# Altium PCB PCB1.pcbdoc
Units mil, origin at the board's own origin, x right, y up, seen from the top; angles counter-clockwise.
Board outline 1838 x 1812 mil, 2 copper layers (Top Layer, Bottom Layer); 12 components, 20 nets, 53 pads, 79 vias.
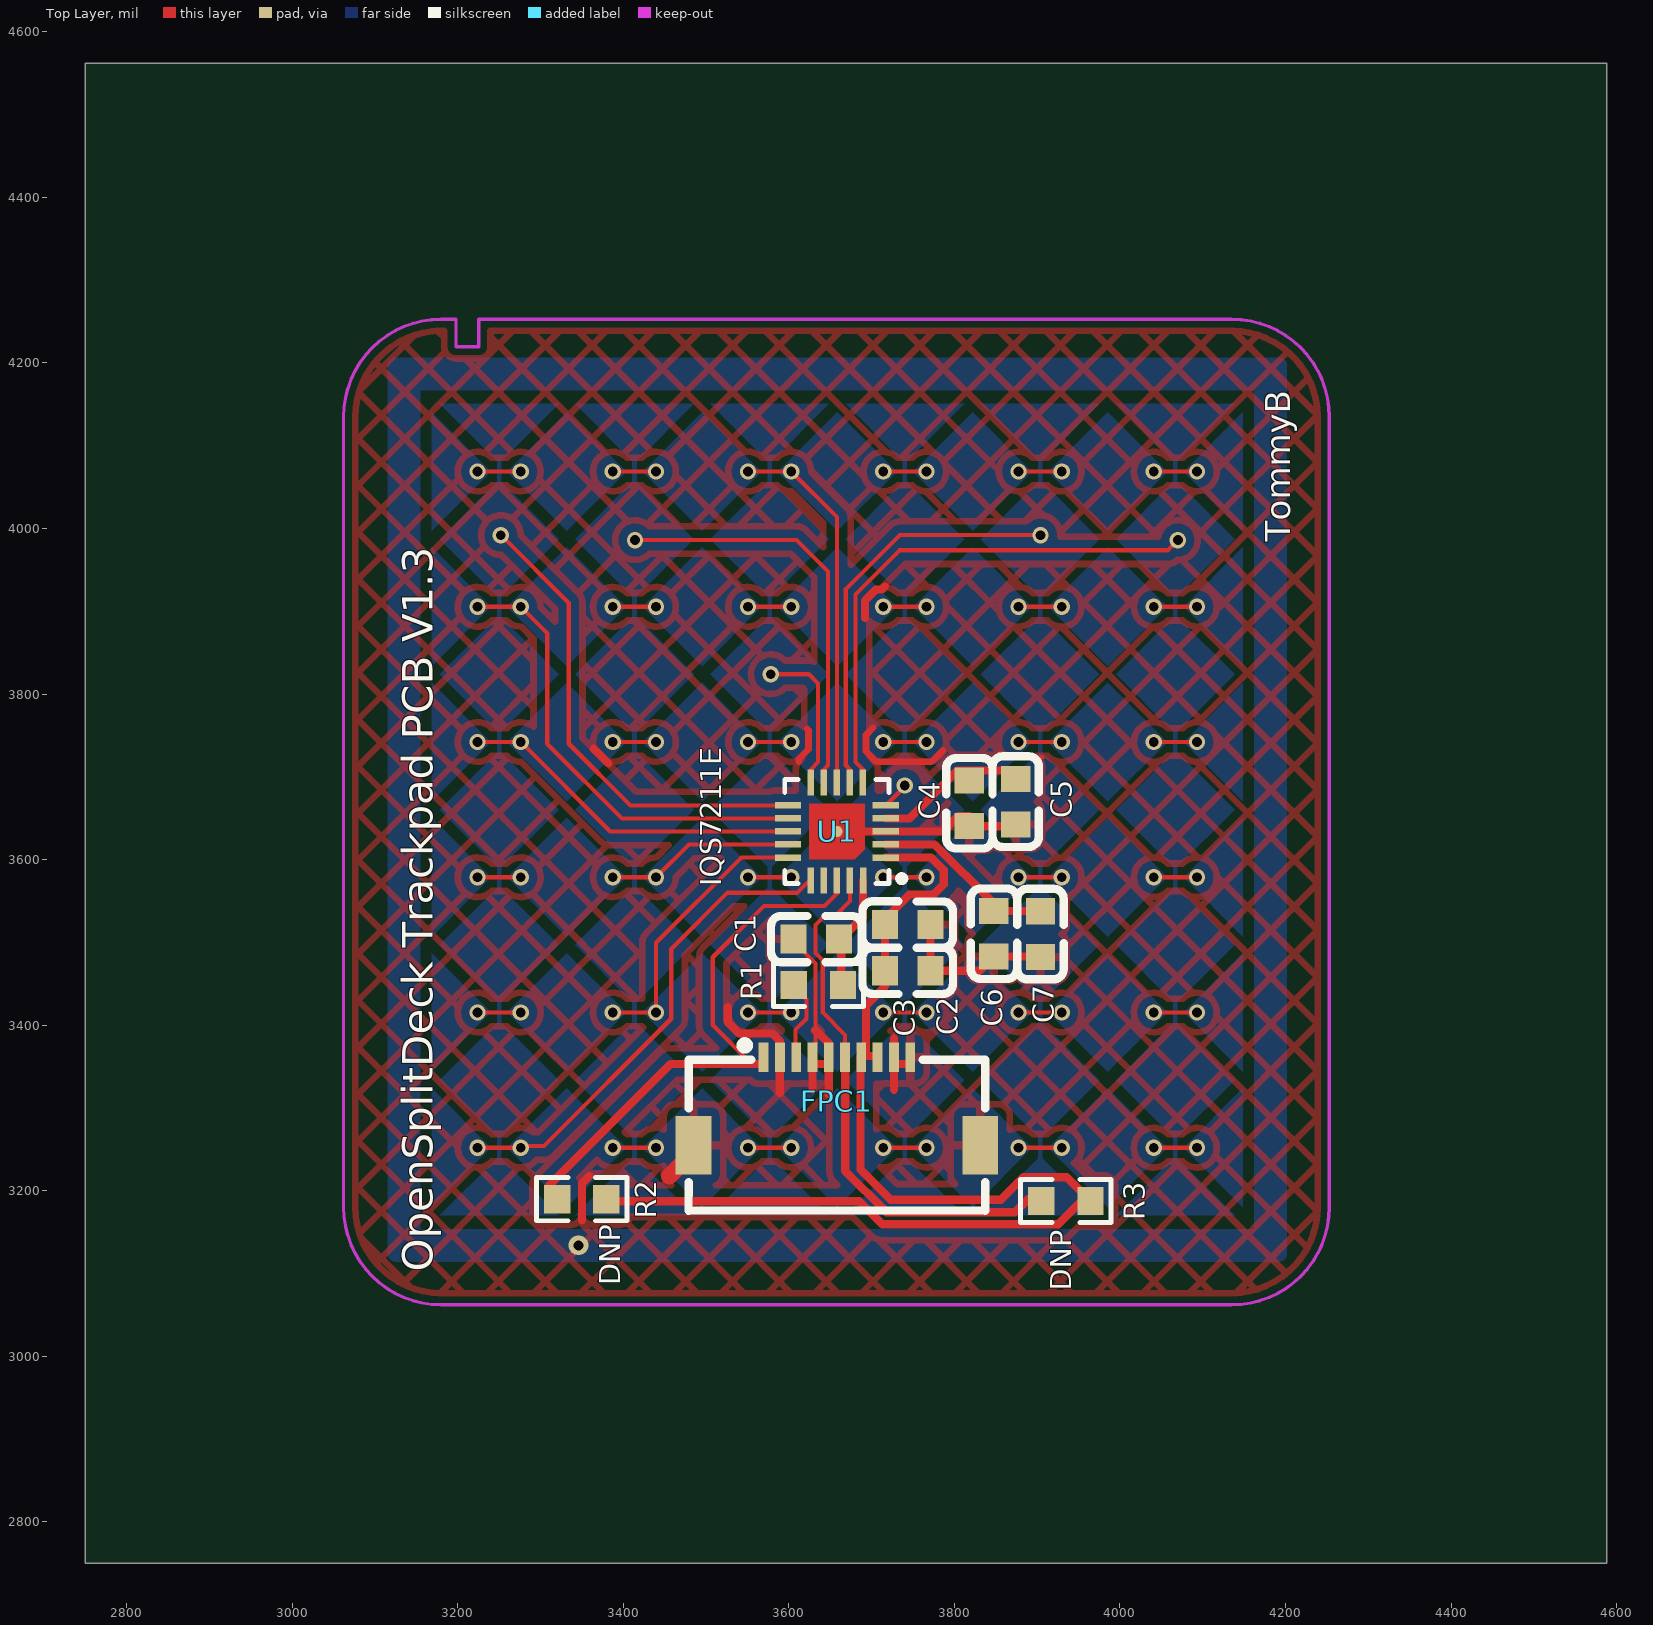
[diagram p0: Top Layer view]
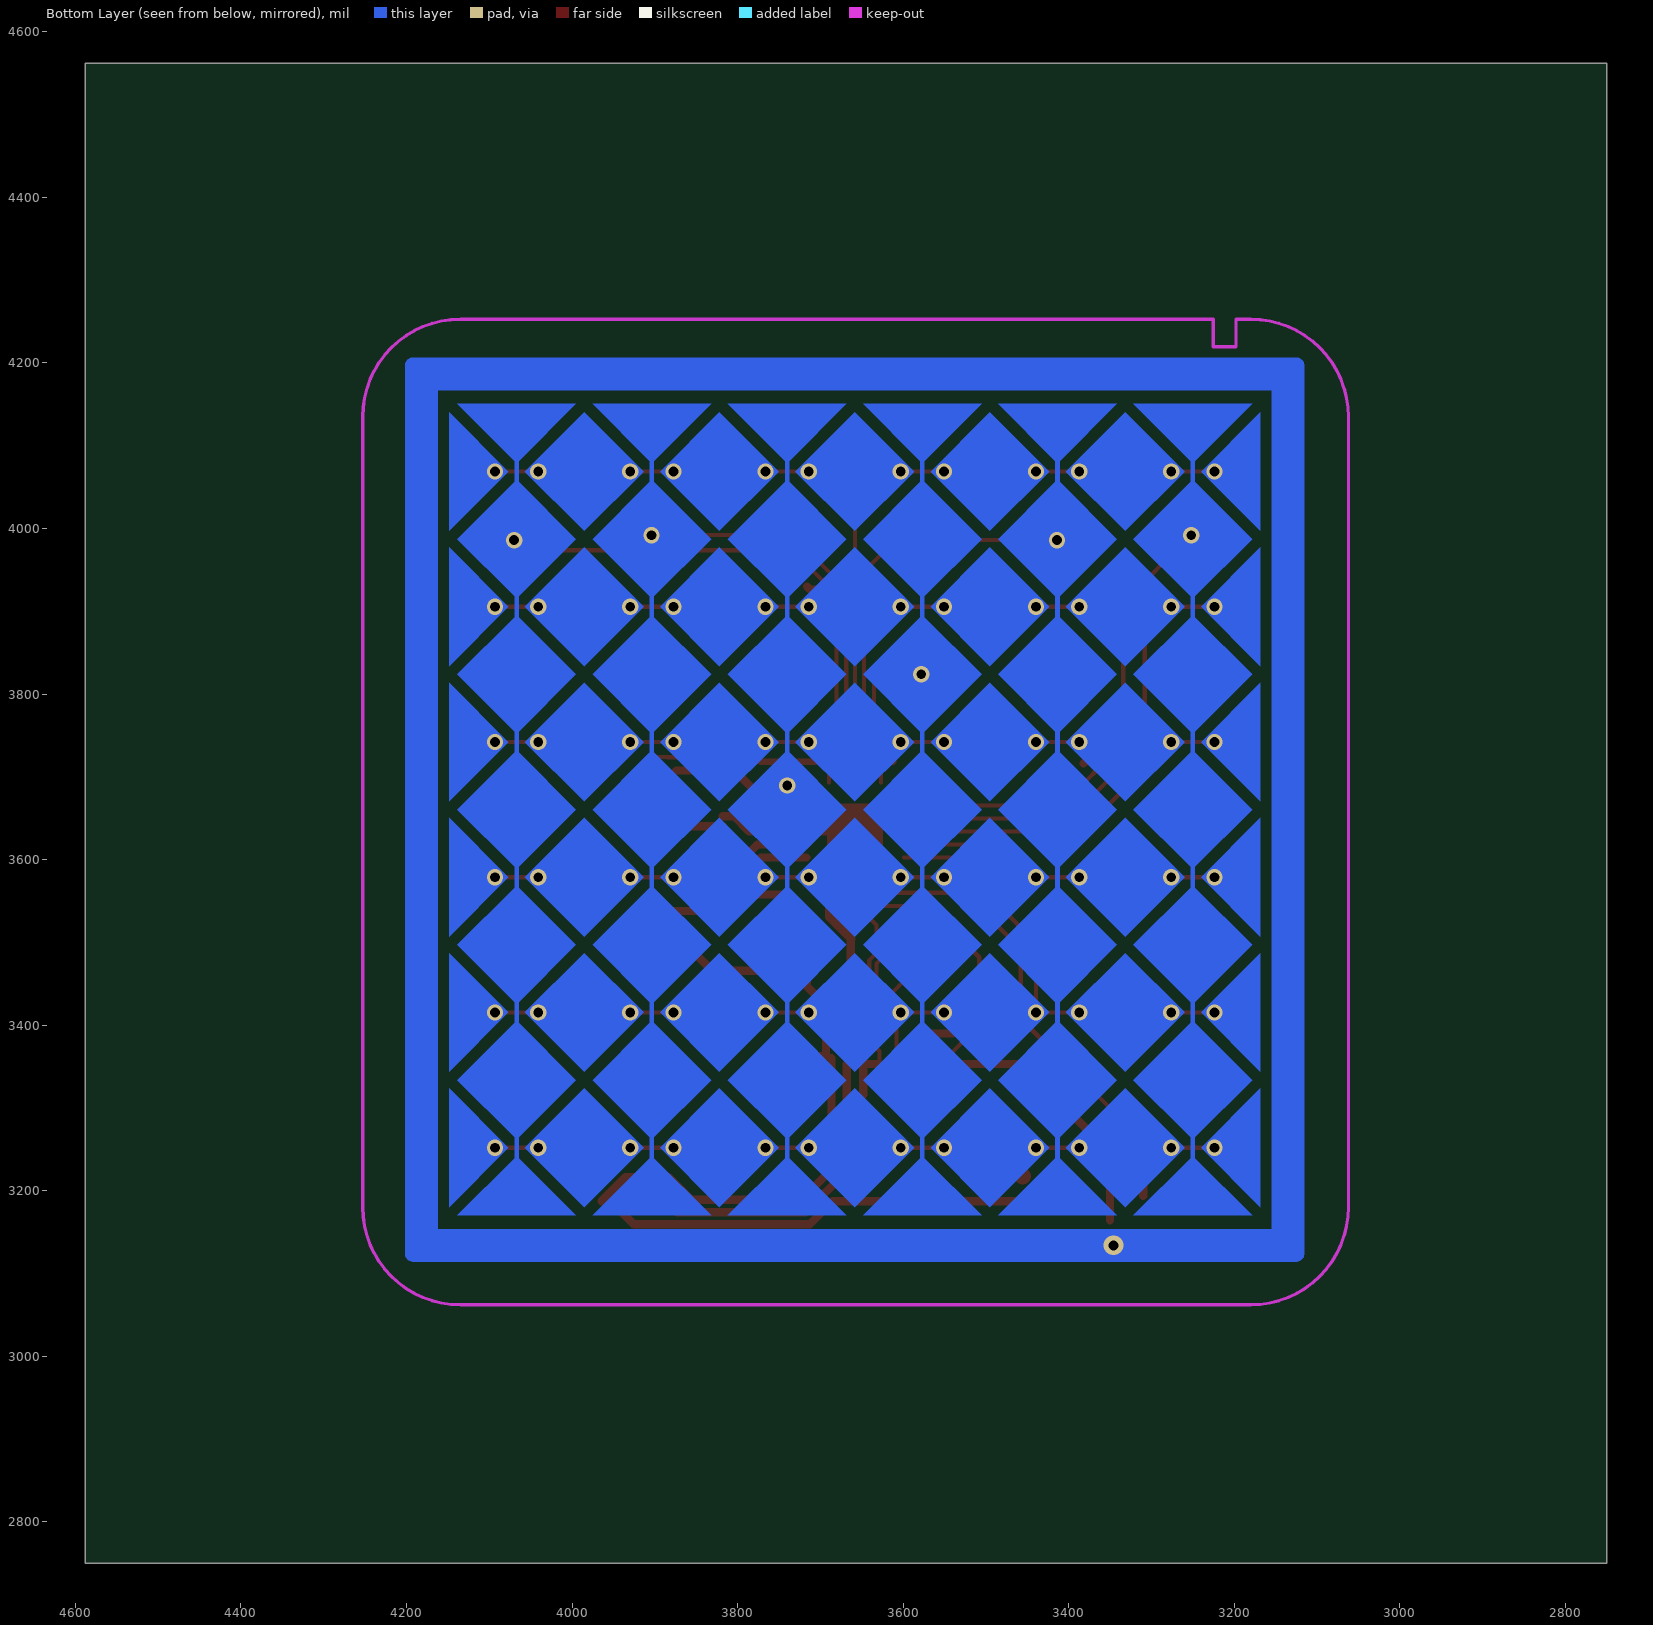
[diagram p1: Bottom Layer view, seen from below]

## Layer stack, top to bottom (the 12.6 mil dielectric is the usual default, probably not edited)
Top Layer: signal copper (thickness not stored)
Dielectric: dielectric 12.6, FR-4, Dk 4.8
Bottom Layer: signal copper (thickness not stored)

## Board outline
4588,2750 2750,2750 2750,4562 4588,4562

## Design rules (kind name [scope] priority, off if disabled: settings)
BoardOutlineClearance copperThickness1oz [All] p0: genericclearance=10 ignorepadtopadclearanceinfootprint=FALSE except(0: Arc-SplitContinuation Track-SplitContinuation SMDPad-SplitContinuation THPad-SplitContinuation Via-SplitContinuation Fill-SplitContinuation Poly-SplitContinuation Region-SplitContinuation Text-SplitContinuation; 6: Track-CutoutEdge SMDPad-CutoutEdge THPad-CutoutEdge Via-CutoutEdge Region-CutoutEdge; 11.8: Track-OutlineEdge SMDPad-OutlineEdge THPad-OutlineEdge Via-OutlineEdge Fill-OutlineEdge Region-OutlineEdge Poly-OutlineEdge Text-OutlineEdge Fill-CutoutEdge)
BoardOutlineClearance copperThickness2oz [All] p0: genericclearance=10 ignorepadtopadclearanceinfootprint=FALSE except(0: Arc-SplitContinuation Track-SplitContinuation SMDPad-SplitContinuation THPad-SplitContinuation Via-SplitContinuation Fill-SplitContinuation Poly-SplitContinuation Region-SplitContinuation Text-SplitContinuation; 6: Track-CutoutEdge SMDPad-CutoutEdge THPad-CutoutEdge Via-CutoutEdge Region-CutoutEdge; 11.8: Track-OutlineEdge SMDPad-OutlineEdge THPad-OutlineEdge Via-OutlineEdge Fill-OutlineEdge Region-OutlineEdge Poly-OutlineEdge Text-OutlineEdge Fill-CutoutEdge)
Clearance copperThickness1oz [(InNet('GND') OR InNet('VCC') OR InNet('RX0') OR InNet('RX1') OR InNet('RX2') OR InNet('RX3') OR InNet('RX4') OR InNet('$1N1973') OR InNet('$1N1718') OR InNet('$1N1697') OR InNet('RX5') OR InNet('TX6') OR InNet('TX8') OR InNet('TX9') OR InNet('TX10') OR InNet('TX11') OR InNet('TX7') OR InNet('SCL') OR InNet('SDA') OR InNet('RDY'))] p1: gap=7 ignorepadtopadclearanceinfootprint=FALSE except(4: Track-Track; 6: Track-SMDPad SMDPad-SMDPad Track-THPad SMDPad-THPad THPad-THPad Track-Via SMDPad-Via THPad-Via Via-Via SMDPad-Fill THPad-Fill Via-Fill Fill-Fill Track-Region SMDPad-Region THPad-Region Via-Region Region-Region Track-Poly SMDPad-Poly THPad-Poly Via-Poly Fill-Poly Region-Poly Poly-Poly Track-Text SMDPad-Text THPad-Text Via-Text Fill-Text Region-Text Poly-Text Text-Text; 6.9: Track-Hole SMDPad-Hole THPad-Hole Via-Hole Fill-Hole Region-Hole Poly-Hole Text-Hole Sheet-Hole; 11.8: Track-Fill Fill-Region Track-Sheet SMDPad-Sheet THPad-Sheet Via-Sheet Fill-Sheet Region-Sheet Poly-Sheet Text-Sheet)
Clearance copperThickness2oz [All] p1: gap=7 ignorepadtopadclearanceinfootprint=FALSE except(6: Track-SMDPad SMDPad-SMDPad Track-THPad SMDPad-THPad THPad-THPad Track-Via SMDPad-Via THPad-Via Via-Via SMDPad-Fill THPad-Fill Via-Fill Fill-Fill Track-Region SMDPad-Region THPad-Region Via-Region Region-Region Track-Poly SMDPad-Poly THPad-Poly Via-Poly Fill-Poly Region-Poly Poly-Poly Track-Text SMDPad-Text THPad-Text Via-Text Fill-Text Region-Text Poly-Text Text-Text; 6.9: Track-Hole SMDPad-Hole THPad-Hole Via-Hole Fill-Hole Region-Hole Poly-Hole Text-Hole Sheet-Hole; 8: Track-Track; 11.8: Track-Fill Fill-Region Track-Sheet SMDPad-Sheet THPad-Sheet Via-Sheet Fill-Sheet Region-Sheet Poly-Sheet Text-Sheet)
DiffPairsRouting differentialPair [All] p1: maxuncoupledlength=10 minlimit=6 maxlimit=6 mostfreqgap=6 toplayer_minwidth=5 toplayer_prefwidth=10 toplayer_maxwidth=100 bottomlayer_minwidth=5 bottomlayer_prefwidth=10 bottomlayer_maxwidth=100
PasteMaskExpansion pasteMaskExpansion [All] p1: expansion=0
PlaneConnect innerPlane [All] p1: planeconnectstyle=Relief reliefexpansion=20 reliefentries=4 reliefconductorwidth=10 reliefairgap=10
PolygonConnect copperRegion [All] p1: connectstyle=Relief reliefentries=4 reliefconductorwidth=10 polygonreliefangle="90 Angle" airgapwidth=10
RoutingVias viaSize [All] p1: viastyle="Through Hole" holewidth=12.0078 minholewidth=11.811 maxholewidth=248.0314 width=24.0158 minwidth=19.685 maxwidth=393.7008
SolderMaskExpansion solderMaskExpansion [All] p1: useseparateexpansions=TRUE expansion=2 expansionbottom=2
Width copperThickness1oz [All] p1: maxlimit=100 minlimit=5 preferedwidth=10
Width copperThickness2oz [All] p1: maxlimit=100 minlimit=8 preferedwidth=10

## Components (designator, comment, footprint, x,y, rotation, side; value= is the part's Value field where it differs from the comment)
C1 "CL10B104KA8NNNC" C0603 3633.12,3504 r0 top
C2 "CL10A475KP8NNNC" C0603 3743.56,3521.56 r180 top
C3 "CC0603JRNPO9BN101" C0603 3743.56,3465.56 r180 top
C4 "CC0603JRNPO9BN101" C0603 3818,3668 r90 top
C5 "CL10A225KP8NNNC" C0603 3874,3670 r90 top
C6 "CC0603JRNPO9BN101" C0603 3847.56,3510.44 r90 top
C7 "CL10A225KP8NNNC" C0603 3904,3510 r90 top
FPC1 "FPC-05F-10PH15" FPC-SMD_10P-P0.50_XUNPU_FPC-05F-10PH15 3658,3308 r0 top
R1 "0603WAF4701T5E" R0603 3635.66,3448.34 r180 top
R2 "0603WAF4701T5E" R0603 3349.66,3189.66 r0 top
R3 "0603WAF4701T5E" R0603 3934.64,3187.32 r0 top
U1 "IQS7211E" UQFN-20_L3.0-W3.0-P0.40-BL-EP1.7 3658,3634 r90 top

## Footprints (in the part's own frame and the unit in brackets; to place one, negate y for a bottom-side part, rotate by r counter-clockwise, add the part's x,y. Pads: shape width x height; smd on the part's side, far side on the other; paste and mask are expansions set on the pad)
C0603 [mm]
  rect 0.8x0.9 smd: 1(-0.7,0) 2(0.7,0)
  silkscreen extent -1.39,-0.71 1.39,0.71
FPC-SMD_10P-P0.50_XUNPU_FPC-05F-10PH15 [mm]
  rect 0.3x0.9 smd: 1(-2.25,1.35) 2(-1.75,1.35) 3(-1.25,1.35) 4(-0.75,1.35) 5(-0.25,1.35) 6(0.25,1.35) 7(0.75,1.35) 8(1.25,1.35) 9(1.75,1.35) 10(2.25,1.35)
  rect 1.1x1.8 smd: 11(4.4,-1.35) 12(-4.4,-1.35)
  silkscreen extent -4.56,-3.36 4.55,1.84
R0603 [mil]
  rect 31.75x34.02 smd: 1(-29.66,0) 2(29.66,0)
  silkscreen extent -55,-26 55,26
UQFN-20_L3.0-W3.0-P0.40-BL-EP1.7 [mm]
  rect 0.2x0.8 smd: 1(-0.8,-1.5) 2(-0.4,-1.5) 3(0,-1.5) 4(0.4,-1.5) 5(0.8,-1.5) 11(0.8,1.5) 12(0.4,1.5) 13(0,1.5) 14(-0.4,1.5) 15(-0.8,1.5)
  rect 0.8x0.2 smd: 6(1.5,-0.8) 7(1.5,-0.4) 8(1.5,0) 9(1.5,0.4) 10(1.5,0.8) 16(-1.5,0.8) 17(-1.5,0.4) 18(-1.5,0) 19(-1.5,-0.4) 20(-1.5,-0.802)
  round 0.34 smd: 21(0,0)
  Top Layer region: 0.85,0.85 0.85,-0.85 -0.55,-0.85 -0.85,-0.55 -0.85,0.85
  silkscreen extent -1.6,-2.09 1.6,1.6

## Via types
v1: diameter 19.7, hole 11.8, Top Layer to Bottom Layer, 78 vias
v2: diameter 24.02, hole 12.01, Top Layer to Bottom Layer, 1 vias

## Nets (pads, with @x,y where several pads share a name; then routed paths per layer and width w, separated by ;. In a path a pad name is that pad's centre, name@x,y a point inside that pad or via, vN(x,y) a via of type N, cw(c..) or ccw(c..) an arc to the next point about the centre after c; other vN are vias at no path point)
$1N1697: C6.2 C7.2 U1.2 | length 225.4
  Top Layer w10: U1.2 3775.96,3618.26 3847.56,3546.65 C6.2 3903.56,3538 C7.2
$1N1718: C4.2 C5.2 U1.4 | length 180.9
  Top Layer w10: U1.4 3745.74,3649.74 3803.56,3707.56 3818,3707.56 C5.2@3874,3707.56
$1N1973: C1.2 R1.1 U1.20 | length 138
  Top Layer w10: R1.1@3663.32,3448.34 3663.32,3503.36 3662.68,3504 3689.27,3530.59 3689.27,3543.83 3689.57,3544.12 U1.20
GND: C1.1 C2.1 C3.1 C4.1 C5.1 C6.1 C7.1 FPC1.2 FPC1.4 FPC1.5 FPC1.9 FPC1.10 FPC1.11 FPC1.12 U1.3 U1.21 | length 1367.1
  Top Layer w5: C1.1 3605.56,3500.91 3632,3474.47 3632,3394 3632,3372 3628.47,3368.47 FPC1.4@3628.47,3353.15 ; 3854,3728 3862,3728 3866,3724 3869.54,3724 3869.82,3723.71 3885.01,3723.71 3885.3,3724 3906,3724
  Top Layer w8: 3612,3718 3612,3721.7 3623.71,3733.42 3623.71,3756.29 3622,3758 ; 3702,3759.48 3693.2,3750.68 3693.2,3730.8 3706,3718 3772,3718 3786,3732
  Top Layer w10: 3350,3164 3350,3208.76 3358.89,3217.65 ; 3364,3734 3382,3716 ; 3526,3422 3526,3404 3540,3390 3580,3390 3589.1,3380.9 3589.1,3353.15 3589.1,3318 ; 3628.47,3322 3628.47,3353.15 FPC1.5@3648.16,3353.15 ; 3632,3394 3648.16,3377.84 FPC1.5@3648.16,3353.15 ; 3648.16,3316 FPC1.5@3648.16,3353.15 ; U1.21 U1.3 3785.99,3633.99 3804.44,3652.44 C4.1@3818,3652.44 ; 3692,3892 3692,3912.86 3705.4,3926.27 3712.27,3926.27 3716,3930 ; 3726.9,3322 FPC1.9@3726.9,3353.15 ; 3726.9,3384 FPC1.9@3726.9,3353.15 ; FPC1.10@3746.58,3353.15 FPC1.9@3726.9,3353.15 ; C2.1 C3.1 3830.24,3465.56 C6.1 3903.56,3482.88 C7.1 C7.1@3904.49,3482.93 ; C4.1 3872,3640.44 C5.1
  Top Layer w20: 3455.57,3217.65 FPC1.12@3484.77,3246.85
  other v2: 3346,3134
RDY: FPC1.3 R1.2 | length 108.1
  Top Layer w5: R1.2@3604,3448.34 3621.21,3431.13 3621.21,3407.68 3608,3394.47 3608,3353.94 FPC1.3@3608.79,3353.15
RX0: U1.5 | length 33.5
  Top Layer w5: U1.5 3740,3688.45 v1(3740,3689.51)
RX1: U1.6 | length 647.8
  Top Layer w5: U1.6 3689.49,3708.99 3680.48,3718 3680.48,3920.48 3733.67,3973.67 4057.67,3973.67 v1(4070,3986)
RX2: U1.7 | length 498
  Top Layer w5: U1.7 3673.74,3709 3668.74,3714 3668.74,3926.74 3734,3992 v1(3904,3992)
RX3: U1.11 | length 581.8
  Top Layer w5: v1(3252,3992) 3334,3910 3334,3740 3408.51,3665.49 U1.11
RX4: U1.9 | length 506
  Top Layer w5: v1(3414,3986) 3609.25,3986 3647.26,3948 3647.26,3713.99 3642.26,3708.99 U1.9
RX5: U1.10 | length 185.2
  Top Layer w5: v1(3578,3824) 3624.01,3824 3635.23,3812.77 3635.23,3717.71 3626.51,3708.99 U1.10
SCL: FPC1.1 R2.1 U1.18 | length 678.8
  Top Layer w5: 3554.85,3353.15 3508,3400 3508,3482 3570,3544 3643,3544 3658.01,3559 U1.18
  Top Layer w10: R2.1@3310,3193.66 3310,3206 3457.15,3353.15 3554.85,3353.15 FPC1.1@3569.42,3353.15
SDA: FPC1.6 R3.1 U1.19 | length 655.8
  Top Layer w5: FPC1.6@3667.84,3353.15 3667.84,3388.16 3640.96,3415.04 3640.96,3478.26 3632,3487.22 3632,3520.78 3641.42,3530.2 3654.2,3530.2 3673.76,3549.76 U1.19
  Top Layer w10: FPC1.6@3667.84,3353.15 3668,3353.15 3668,3224 3718,3174 3873.07,3174 3888.61,3189.54 3902.76,3189.54 R3.1
TX6: U1.8 | length 712
  Top Layer w5: v1(3223.88,4068.82) v1(3276.11,4068.82) ; v1(3387.26,4068.82) v1(3439.49,4068.82) ; v1(3550.65,4068.82) v1(3602.88,4068.82) 3658.01,4013.69 U1.8 ; v1(3714.03,4068.82) v1(3766.27,4068.82) ; v1(3877.42,4068.82) v1(3929.65,4068.82) ; v1(4040.8,4068.82) v1(4093.04,4068.82)
TX7: U1.12 | length 820.4
  Top Layer w5: v1(3223.88,3905.43) v1(3276.11,3905.43) 3308,3873.54 3308,3740 3398.26,3649.74 U1.12 ; v1(3387.26,3905.43) v1(3439.49,3905.43) ; v1(3550.65,3905.43) v1(3602.88,3905.43) ; v1(3714.03,3905.43) v1(3766.27,3905.43) ; v1(3877.42,3905.43) v1(3929.65,3905.43) ; v1(4040.8,3905.43) v1(4093.04,3905.43)
TX8: U1.13 | length 681
  Top Layer w5: v1(3223.88,3742.05) v1(3276.11,3742.05) 3384.16,3633.99 U1.13 ; v1(3387.26,3742.05) v1(3439.49,3742.05) ; v1(3550.65,3742.05) v1(3602.88,3742.05) ; v1(3714.03,3742.05) v1(3766.27,3742.05) ; v1(3877.42,3742.05) v1(3929.65,3742.05) ; v1(4040.8,3742.05) v1(4093.04,3742.05)
TX9: U1.14 | length 489.3
  Top Layer w5: v1(3223.88,3578.66) v1(3276.11,3578.66) ; v1(3387.26,3578.66) v1(3439.49,3578.66) 3479.09,3618.26 U1.14 ; v1(3550.65,3578.66) v1(3602.88,3578.66) ; v1(3714.03,3578.66) v1(3766.27,3578.66) ; v1(3877.42,3578.66) v1(3929.65,3578.66) ; v1(4040.8,3578.66) v1(4093.04,3578.66)
TX10: U1.15 | length 599.7
  Top Layer w5: v1(3223.88,3415.27) v1(3276.11,3415.27) ; v1(3387.26,3415.27) v1(3439.49,3415.27) 3439.49,3499.49 3542.51,3602.51 U1.15 ; v1(3550.65,3415.27) v1(3602.88,3415.27) ; v1(3714.03,3415.27) v1(3766.27,3415.27) ; v1(3877.42,3415.27) v1(3929.65,3415.27) ; v1(4040.8,3415.27) v1(4093.04,3415.27)
TX11: U1.16 | length 846.9
  Top Layer w5: v1(3223.88,3251.89) v1(3276.11,3251.89) 3278.11,3253.89 3304.04,3253.89 3457.83,3407.68 3457.83,3491.83 3526,3560 3610.15,3560 3625.09,3574.95 U1.16 ; v1(3387.26,3251.89) v1(3439.49,3251.89) ; v1(3550.65,3251.89) v1(3602.88,3251.89) ; v1(3714.03,3251.89) v1(3766.27,3251.89) ; v1(3877.42,3251.89) v1(3929.65,3251.89) ; v1(4040.8,3251.89) v1(4093.04,3251.89)
VCC: C2.2 C3.2 FPC1.7 FPC1.8 R2.2 R3.2 U1.1 | length 1428.9
  Top Layer w10: R2.2 3381.66,3187.32 3684.86,3187.32 3712.85,3159.33 3925.41,3159.33 3953.4,3187.32 R3.2 3935.31,3216.31 3883.55,3216.31 3856.26,3189.02 3722.81,3189.02 3686.53,3225.29 FPC1.7@3686.53,3359.82 ; FPC1.8@3705.56,3362.8 3693.2,3362.8 3693.2,3423.9 3716,3446.71 C3.2 3716,3528 3745.83,3557.83 3774.9,3557.83 3787.1,3570.03 3787.1,3587.29 3771.89,3602.51 U1.1
pads on no net: U1.17

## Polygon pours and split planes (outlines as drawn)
GND on Top Layer (hatched 45Degree grid 40 track 8, remove dead copper, pour order 0): 3000,4312 4338,4312 4338,3000 3000,3000

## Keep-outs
Board Outline Layer:
  lines w3.94: 3062,3180.11 3062,4134.83 cw(c3180.11,4134.83) 3180.11,4252.94 3197.83,4252.94 3197.83,4219.57 3225.39,4219.57 3225.39,4252.94 4134.83,4252.94 cw(c4134.83,4134.83) 4252.94,4134.83 4252.94,3180.11 cw(c4134.83,3180.11) 4134.83,3062 3180.11,3062 cw(c3180.11,3180.11) 3062,3180.11

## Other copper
Bottom Layer:
  region net GND: 3125.15,4206.54 4191.76,4206.54 cw(c4191.76,4196.54) 4201.76,4196.54 4201.76,4177.17 cw(c4191.76,4177.17) 4191.76,4167.17 3125.15,4167.17 cw(c3125.15,4177.17) 3115.15,4177.17 3115.15,4196.54 cw(c3125.15,4196.54)
  region net GND: 4172.39,4206.54 4191.76,4206.54 cw(c4191.76,4196.54) 4201.76,4196.54 4201.76,3124.17 cw(c4191.76,3124.17) 4191.76,3114.17 4172.39,3114.17 cw(c4172.39,3124.17) 4162.39,3124.17 4162.39,4196.54 cw(c4172.39,4196.54)
  region net GND: 3125.15,3153.54 4191.76,3153.54 cw(c4191.76,3143.54) 4201.76,3143.54 4201.76,3124.17 cw(c4191.76,3124.17) 4191.76,3114.17 3125.15,3114.17 cw(c3125.15,3124.17) 3115.15,3124.17 3115.15,3143.54 cw(c3125.15,3143.54)
  region net GND: 3125.15,4206.54 3144.52,4206.54 cw(c3144.52,4196.54) 3154.52,4196.54 3154.52,3124.17 cw(c3144.52,3124.17) 3144.52,3114.17 3125.15,3114.17 cw(c3125.15,3124.17) 3115.15,3124.17 3115.15,4196.54 cw(c3125.15,4196.54)
  region net RX3: 3178.31,3170.2 3321.68,3170.2 3252.51,3239.36 3252.51,3264.42 3321.68,3333.58 3252.51,3402.75 3252.51,3427.8 3321.68,3496.97 3252.51,3566.13 3252.51,3591.19 3321.68,3660.35 3252.51,3729.52 3252.51,3754.57 3321.68,3823.74 3252.51,3892.9 3252.51,3917.96 3321.68,3987.12 3252.51,4056.29 3252.51,4081.34 3321.68,4150.51 3178.31,4150.51 3247.47,4081.34 3247.47,4056.29 3178.31,3987.12 3247.47,3917.96 3247.47,3892.9 3178.31,3823.74 3247.47,3754.57 3247.47,3729.52 3178.31,3660.35 3247.47,3591.19 3247.47,3566.13 3178.31,3496.97 3247.47,3427.8 3247.47,3402.75 3178.31,3333.58 3247.47,3264.42 3247.47,3239.36
  region net TX11: 3331.68,3180.2 3260,3251.89 3331.68,3323.57 3403.37,3251.89
  region net TX11: 3168.3,3180.2 3239.98,3251.89 3168.3,3323.57
  region net RX4: 3341.69,3170.2 3485.06,3170.2 3415.9,3239.36 3415.9,3264.42 3485.06,3333.58 3415.9,3402.75 3415.9,3427.8 3485.06,3496.97 3415.9,3566.13 3415.9,3591.19 3485.06,3660.35 3415.9,3729.52 3415.9,3754.57 3485.06,3823.74 3415.9,3892.9 3415.9,3917.96 3485.06,3987.12 3415.9,4056.29 3415.9,4081.34 3485.06,4150.51 3341.69,4150.51 3410.86,4081.34 3410.86,4056.29 3341.69,3987.12 3410.86,3917.96 3410.86,3892.9 3341.69,3823.74 3410.86,3754.57 3410.86,3729.52 3341.69,3660.35 3410.86,3591.19 3410.86,3566.13 3341.69,3496.97 3410.86,3427.8 3410.86,3402.75 3341.69,3333.58 3410.86,3264.42 3410.86,3239.36
  region net TX11: 3495.07,3180.2 3423.39,3251.89 3495.07,3323.57 3566.76,3251.89
  region net RX5: 3505.08,3170.2 3648.45,3170.2 3579.28,3239.36 3579.28,3264.42 3648.45,3333.58 3579.28,3402.75 3579.28,3427.8 3648.45,3496.97 3579.28,3566.13 3579.28,3591.19 3648.45,3660.35 3579.28,3729.52 3579.28,3754.57 3648.45,3823.74 3579.28,3892.9 3579.28,3917.96 3648.45,3987.12 3579.28,4056.29 3579.28,4081.34 3648.45,4150.51 3505.08,4150.51 3574.24,4081.34 3574.24,4056.29 3505.08,3987.12 3574.24,3917.96 3574.24,3892.9 3505.08,3823.74 3574.24,3754.57 3574.24,3729.52 3505.08,3660.35 3574.24,3591.19 3574.24,3566.13 3505.08,3496.97 3574.24,3427.8 3574.24,3402.75 3505.08,3333.58 3574.24,3264.42 3574.24,3239.36
  region net TX11: 3658.46,3180.2 3586.77,3251.89 3658.46,3323.57 3730.14,3251.89
  region net RX0: 3668.46,3170.2 3811.83,3170.2 3742.67,3239.36 3742.67,3264.42 3811.83,3333.58 3742.67,3402.75 3742.67,3427.8 3811.83,3496.97 3742.67,3566.13 3742.67,3591.19 3811.83,3660.35 3742.67,3729.52 3742.67,3754.57 3811.83,3823.74 3742.67,3892.9 3742.67,3917.96 3811.83,3987.12 3742.67,4056.29 3742.67,4081.34 3811.83,4150.51 3668.46,4150.51 3737.63,4081.34 3737.63,4056.29 3668.46,3987.12 3737.63,3917.96 3737.63,3892.9 3668.46,3823.74 3737.63,3754.57 3737.63,3729.52 3668.46,3660.35 3737.63,3591.19 3737.63,3566.13 3668.46,3496.97 3737.63,3427.8 3737.63,3402.75 3668.46,3333.58 3737.63,3264.42 3737.63,3239.36
  region net TX11: 3821.84,3180.2 3750.16,3251.89 3821.84,3323.57 3893.53,3251.89
  region net RX2: 3831.85,3170.2 3975.22,3170.2 3906.06,3239.36 3906.06,3264.42 3975.22,3333.58 3906.06,3402.75 3906.06,3427.8 3975.22,3496.97 3906.06,3566.13 3906.06,3591.19 3975.22,3660.35 3906.06,3729.52 3906.06,3754.57 3975.22,3823.74 3906.06,3892.9 3906.06,3917.96 3975.22,3987.12 3906.06,4056.29 3906.06,4081.34 3975.22,4150.51 3831.85,4150.51 3901.02,4081.34 3901.02,4056.29 3831.85,3987.12 3901.02,3917.96 3901.02,3892.9 3831.85,3823.74 3901.02,3754.57 3901.02,3729.52 3831.85,3660.35 3901.02,3591.19 3901.02,3566.13 3831.85,3496.97 3901.02,3427.8 3901.02,3402.75 3831.85,3333.58 3901.02,3264.42 3901.02,3239.36
  region net TX11: 3985.23,3180.2 3913.54,3251.89 3985.23,3323.57 4056.91,3251.89
  region net RX1: 3995.24,3170.2 4138.61,3170.2 4069.44,3239.36 4069.44,3264.42 4138.61,3333.58 4069.44,3402.75 4069.44,3427.8 4138.61,3496.97 4069.44,3566.13 4069.44,3591.19 4138.61,3660.35 4069.44,3729.52 4069.44,3754.57 4138.61,3823.74 4069.44,3892.9 4069.44,3917.96 4138.61,3987.12 4069.44,4056.29 4069.44,4081.34 4138.61,4150.51 3995.24,4150.51 4064.4,4081.34 4064.4,4056.29 3995.24,3987.12 4064.4,3917.96 4064.4,3892.9 3995.24,3823.74 4064.4,3754.57 4064.4,3729.52 3995.24,3660.35 4064.4,3591.19 4064.4,3566.13 3995.24,3496.97 4064.4,3427.8 4064.4,3402.75 3995.24,3333.58 4064.4,3264.42 4064.4,3239.36
  region net TX11: 4148.61,3323.57 4076.93,3251.89 4148.61,3180.2
  region net TX10: 3168.3,3343.59 3239.98,3415.27 3168.3,3486.96
  region net TX10: 3331.68,3343.59 3260,3415.27 3331.68,3486.96 3403.37,3415.27
  region net TX10: 3495.07,3343.59 3423.39,3415.27 3495.07,3486.96 3566.76,3415.27
  region net TX10: 3658.46,3343.59 3586.77,3415.27 3658.46,3486.96 3730.14,3415.27
  region net TX10: 3821.84,3343.59 3750.16,3415.27 3821.84,3486.96 3893.53,3415.27
  region net TX10: 3985.23,3343.59 3913.54,3415.27 3985.23,3486.96 4056.91,3415.27
  region net TX10: 4148.61,3486.96 4076.93,3415.27 4148.61,3343.59
  region net TX9: 3168.3,3506.97 3239.98,3578.66 3168.3,3650.34
  region net TX9: 3331.68,3506.97 3260,3578.66 3331.68,3650.34 3403.37,3578.66
  region net TX9: 3495.07,3506.97 3423.39,3578.66 3495.07,3650.34 3566.76,3578.66
  region net TX9: 3658.46,3506.97 3586.77,3578.66 3658.46,3650.34 3730.14,3578.66
  region net TX9: 3821.84,3506.97 3750.16,3578.66 3821.84,3650.34 3893.53,3578.66
  region net TX9: 3985.23,3506.97 3913.54,3578.66 3985.23,3650.34 4056.91,3578.66
  region net TX9: 4148.61,3650.34 4076.93,3578.66 4148.61,3506.97
  region net TX8: 3168.3,3670.36 3239.98,3742.05 3168.3,3813.73
  region net TX8: 3331.68,3670.36 3260,3742.05 3331.68,3813.73 3403.37,3742.05
  region net TX8: 3495.07,3670.36 3423.39,3742.05 3495.07,3813.73 3566.76,3742.05
  region net TX8: 3658.46,3670.36 3586.77,3742.05 3658.46,3813.73 3730.14,3742.05
  region net TX8: 3821.84,3670.36 3750.16,3742.05 3821.84,3813.73 3893.53,3742.05
  region net TX8: 3985.23,3670.36 3913.54,3742.05 3985.23,3813.73 4056.91,3742.05
  region net TX8: 4148.61,3813.73 4076.93,3742.05 4148.61,3670.36
  region net TX7: 3168.3,3833.75 3239.98,3905.43 3168.3,3977.12
  region net TX7: 3331.68,3833.75 3260,3905.43 3331.68,3977.12 3403.37,3905.43
  region net TX7: 3495.07,3833.75 3423.39,3905.43 3495.07,3977.12 3566.76,3905.43
  region net TX7: 3658.46,3833.75 3586.77,3905.43 3658.46,3977.12 3730.14,3905.43
  region net TX7: 3821.84,3833.75 3750.16,3905.43 3821.84,3977.12 3893.53,3905.43
  region net TX7: 3985.23,3833.75 3913.54,3905.43 3985.23,3977.12 4056.91,3905.43
  region net TX7: 4148.61,3977.12 4076.93,3905.43 4148.61,3833.75
  region net TX6: 3168.3,3997.13 3239.98,4068.82 3168.3,4140.5
  region net TX6: 3331.68,3997.13 3260,4068.82 3331.68,4140.5 3403.37,4068.82
  region net TX6: 3495.07,3997.13 3423.39,4068.82 3495.07,4140.5 3566.76,4068.82
  region net TX6: 3658.46,3997.13 3586.77,4068.82 3658.46,4140.5 3730.14,4068.82
  region net TX6: 3821.84,3997.13 3750.16,4068.82 3821.84,4140.5 3893.53,4068.82
  region net TX6: 3985.23,3997.13 3913.54,4068.82 3985.23,4140.5 4056.91,4068.82
  region net TX6: 4148.61,4140.5 4076.93,4068.82 4148.61,3997.13

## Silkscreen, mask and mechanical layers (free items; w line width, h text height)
Top Silkscreen Layer:
  text "TommyB" at 4206,3984 h30 r90
  text "OpenSplitDeck Trackpad PCB V1.3" at 3170,3102 h37 r90
  text "DNP" at 3396,3086 h25 r90
  text "DNP" at 3941.13,3079.32 h25 r90
Bottom Solder Mask Layer:
  region: 3111.37,3167.32 4205.54,3167.32 cw(c4205.54,3157.32) 4215.54,3157.32 4215.54,3110.39 cw(c4205.54,3110.39) 4205.54,3100.39 3111.37,3100.39 cw(c3111.37,3110.39) 3101.37,3110.39 3101.37,3157.32 cw(c3111.37,3157.32)
  region: 4158.61,4220.32 4205.54,4220.32 cw(c4205.54,4210.32) 4215.54,4210.32 4215.54,3110.39 cw(c4205.54,3110.39) 4205.54,3100.39 4158.61,3100.39 cw(c4158.61,3110.39) 4148.61,3110.39 4148.61,4210.32 cw(c4158.61,4210.32)
  region: 3111.37,4220.32 4205.54,4220.32 cw(c4205.54,4210.32) 4215.54,4210.32 4215.54,4163.39 cw(c4205.54,4163.39) 4205.54,4153.39 3111.37,4153.39 cw(c3111.37,4163.39) 3101.37,4163.39 3101.37,4210.32 cw(c3111.37,4210.32)
  region: 3111.37,4220.32 3158.3,4220.32 cw(c3158.3,4210.32) 3168.3,4210.32 3168.3,3110.39 cw(c3158.3,3110.39) 3158.3,3100.39 3111.37,3100.39 cw(c3111.37,3110.39) 3101.37,3110.39 3101.37,4210.32 cw(c3111.37,4210.32)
